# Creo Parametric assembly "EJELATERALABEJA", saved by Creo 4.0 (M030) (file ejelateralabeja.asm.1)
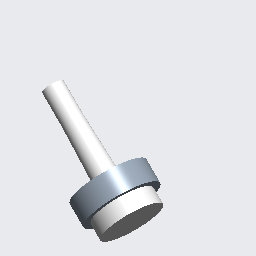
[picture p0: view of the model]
Units: millimeter Newton Second (mmNs); MM, TONNE, SECS

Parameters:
  MODELED_BY = "aj"

Created from: MMNS_ASM_DESIGN.ASM

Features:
  1. datum plane "ASM_RIGHT"
  2. datum plane "ASM_TOP"
  3. datum plane "ASM_FRONT"
  4. coordinate system
  5. component "EJERUEDASLATERALABEJA"
  6. component "RODAMIENTOABEJA"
